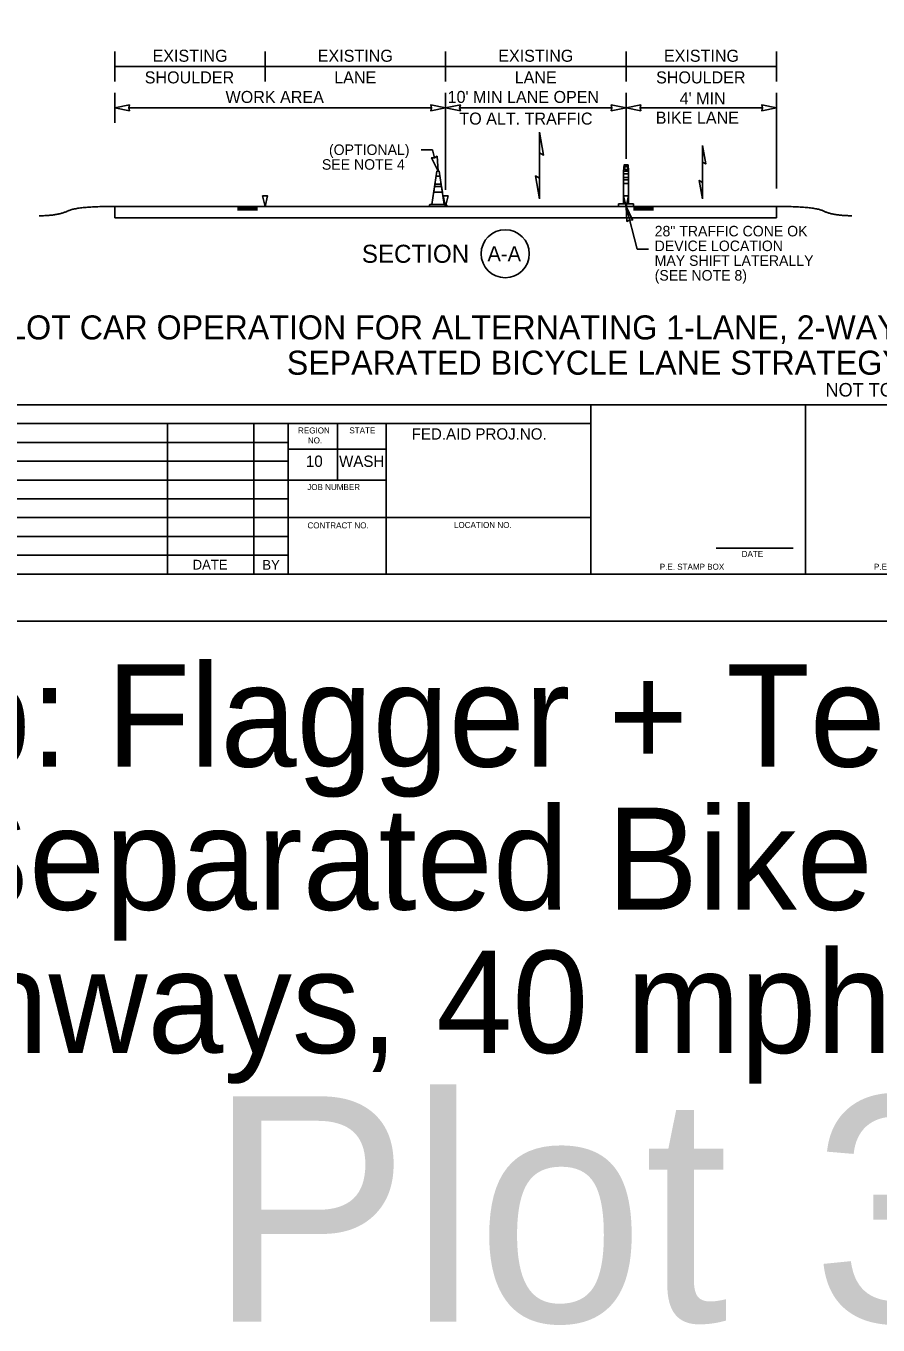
# Model space of a CAD drawing. Extents: x 99998.9 to 100095.7, y 99995 to 100010.7.
# Drawn here: x 100043.7 to 100049.37, y 99995.01 to 100003.65 of the extents above; entities that cross this region are included whole.
import ezdxf

# ---------------------------------------------------------------- set-up
doc = ezdxf.new("R2010")
doc.units = 0
for name, color, linetype in [('SH_DE_DetailHeading1Text', 7, 'Continuous'), ('SH_GI_PlotLimits', 7, 'Continuous'), ('SH_GI_SheetBorder', 7, 'Continuous'), ('SH_GI_SheetLocationText', 7, 'Continuous'), ('SH_GI_SheetTextInCells', 7, 'Continuous'), ('TR_WZ_TrafficConeElev', 7, 'Continuous'), ('TR_WZ_TubularMarkerElev', 7, 'Continuous'), ('TR_WZ_WorkZoneDetails', 7, 'Continuous'), ('TR_WZ_WorkZoneTextCurrent', 7, 'Continuous')]:
    doc.layers.add(name, color=color, linetype=linetype)

msp = doc.modelspace()

# ---------------------------------------------------------------- linework, layer by layer
at = {"layer": 'SH_GI_PlotLimits'}
msp.add_lwpolyline([(100039.0625, 99999.6875), (100056.0625, 99999.6875), (100056.0625, 100010.6875), (100039.0625, 100010.6875)], close=True, dxfattribs=at)
at = {"layer": 'SH_GI_SheetBorder'}
for p, q in [((100040, 100001.1259), (100055.75, 100001.1259)), ((100047.4566, 100000), (100047.4566, 100001.1259)), ((100048.8828, 100000), (100048.8828, 100001.1259)), ((100040, 100001.0008), (100047.4566, 100001.0008)), ((100044.641, 100001.0008), (100044.641, 100000)), ((100045.2164, 100001.0008), (100045.2164, 100000)), ((100045.4451, 100001.0008), (100045.4451, 100000)), ((100045.7719, 100000.6255), (100045.7719, 100001.0008)), ((100046.0956, 100000), (100046.0956, 100001.0008)), ((100042.1821, 100000.8757), (100045.4466, 100000.8757)), ((100042.1821, 100000.7506), (100045.4466, 100000.7506)), ((100046.0958, 100000.831), (100045.4466, 100000.831)), ((100040, 100000.6255), (100045.4466, 100000.6255)), ((100046.0958, 100000.6255), (100045.4466, 100000.6255)), ((100040, 100000.5004), (100045.4466, 100000.5004)), ((100040, 100000.3753), (100045.4466, 100000.3753)), ((100047.4566, 100000.3753), (100045.4466, 100000.3753)), ((100040, 100000.2502), (100045.4466, 100000.2502)), ((100048.2903, 100000.1733), (100048.802, 100000.1733)), ((100040, 100000.1251), (100045.4466, 100000.1251)), ((100040, 100000), (100055.75, 100000))]:
    msp.add_line(p, q, dxfattribs=at)
at = {"layer": 'TR_WZ_TrafficConeElev'}
for p, q in [((100046.4173, 100002.5768), (100046.4116, 100002.5393)), ((100046.4642, 100002.5768), (100046.4173, 100002.5768)), ((100046.4282, 100002.6476), (100046.4199, 100002.5934)), ((100046.4199, 100002.5934), (100046.4617, 100002.5934)), ((100046.4534, 100002.6476), (100046.4282, 100002.6476)), ((100046.4617, 100002.5934), (100046.4534, 100002.6476)), ((100046.47, 100002.5393), (100046.4642, 100002.5768)), ((100046.4116, 100002.5393), (100046.47, 100002.5393)), ((100046.3871, 100002.458), (100046.383, 100002.4538)), ((100046.383, 100002.4538), (100046.383, 100002.4455)), ((100046.383, 100002.4455), (100046.4986, 100002.4455)), ((100046.3991, 100002.458), (100046.3871, 100002.458)), ((100046.4986, 100002.4538), (100046.4944, 100002.458)), ((100046.4986, 100002.4455), (100046.4986, 100002.4538))]:
    msp.add_line(p, q, dxfattribs=at)
msp.add_lwpolyline([(100046.3991, 100002.458), (100046.4824, 100002.458), (100046.4486, 100002.6788), (100046.433, 100002.6788)], close=True, dxfattribs=at)
msp.add_lwpolyline([(100046.3991, 100002.458), (100046.4824, 100002.458), (100046.4486, 100002.6788), (100046.433, 100002.6788)], close=True, dxfattribs=at)
msp.add_lwpolyline([(100046.4944, 100002.458), (100046.4824, 100002.458), (100046.3991, 100002.458)], dxfattribs=at)
at = {"layer": 'TR_WZ_TubularMarkerElev'}
for p, q in [((100047.7074, 100002.6625), (100047.6741, 100002.6625)), ((100047.6741, 100002.6625), (100047.6741, 100002.6379)), ((100047.6743, 100002.6788), (100047.7072, 100002.6788)), ((100047.6824, 100002.7112), (100047.6998, 100002.7112)), ((100047.6998, 100002.689), (100047.6824, 100002.689)), ((100047.7074, 100002.6379), (100047.7074, 100002.6625)), ((100047.6741, 100002.6379), (100047.7074, 100002.6379)), ((100047.6741, 100002.6215), (100047.6741, 100002.597)), ((100047.7074, 100002.6215), (100047.6741, 100002.6215)), ((100047.6741, 100002.597), (100047.7074, 100002.597)), ((100047.7074, 100002.597), (100047.7074, 100002.6215)), ((100047.6408, 100002.4619), (100047.6408, 100002.4455)), ((100047.6408, 100002.4455), (100047.7408, 100002.4455)), ((100047.7408, 100002.4455), (100047.7408, 100002.4619))]:
    msp.add_line(p, q, dxfattribs=at)
for points in [[(100047.6741, 100002.4619), (100047.7074, 100002.4619), (100047.7074, 100002.6747)], [(100047.6741, 100002.6747), (100047.6741, 100002.4619)], [(100047.6741, 100002.4619), (100047.7074, 100002.4619), (100047.7074, 100002.6747)], [(100047.6741, 100002.6747), (100047.6741, 100002.4619)], [(100047.7072, 100002.6788), (100047.6743, 100002.6788), (100047.7072, 100002.6788), (100047.6743, 100002.6788)], [(100047.7072, 100002.6788), (100047.6743, 100002.6788), (100047.7072, 100002.6788), (100047.6743, 100002.6788)], [(100047.7408, 100002.4619), (100047.7074, 100002.4619), (100047.6741, 100002.4619), (100047.6408, 100002.4619)]]:
    msp.add_lwpolyline(points, dxfattribs=at)
msp.add_lwpolyline([(100047.6743, 100002.6788), (100047.6774, 100002.7213), (100047.7044, 100002.7213), (100047.7072, 100002.6788)], close=True, dxfattribs=at)
for centre, major_axis, ratio, start_param, end_param in [((100047.6744, 100002.6738), (0, 0.00512), 0.053405, 0.177149, 1.393647), ((100047.6744, 100002.6738), (0, 0.00512), 0.053405, 0.177149, 1.393647), ((100047.6824, 100002.7001), (0, 0.0111), 0.071484, 0, 3.141593), ((100047.6998, 100002.7001), (0, 0.0111), 0.071484, 3.141593, 6.283185), ((100047.7072, 100002.6738), (0, 0.00512), 0.053405, 4.889538, 6.106036), ((100047.7072, 100002.6738), (0, 0.00512), 0.053405, 4.889538, 6.106036)]:
    msp.add_ellipse(centre, major_axis=major_axis, ratio=ratio, start_param=start_param, end_param=end_param, dxfattribs=at)
at = {"layer": 'TR_WZ_WorkZoneDetails'}
for p, q in [((100044.2907, 100003.2755), (100044.2907, 100003.4755)), ((100045.2907, 100003.2755), (100045.2907, 100003.4755)), ((100046.4907, 100003.2755), (100046.4907, 100003.4755)), ((100047.6907, 100003.2755), (100047.6907, 100003.4755)), ((100048.6907, 100003.2755), (100048.6907, 100003.4755)), ((100044.2907, 100003.3755), (100045.2907, 100003.3755)), ((100045.2907, 100003.3755), (100046.4907, 100003.3755)), ((100046.4907, 100003.3755), (100047.6907, 100003.3755)), ((100047.6907, 100003.3755), (100048.6907, 100003.3755)), ((100044.2907, 100003.0015), (100044.2907, 100003.2015)), ((100046.4907, 100002.5552), (100046.4907, 100003.2015)), ((100047.6907, 100002.7613), (100047.6907, 100003.2015)), ((100048.6907, 100002.5652), (100048.6907, 100003.2015)), ((100046.397, 100003.1015), (100044.3844, 100003.1015)), ((100047.5969, 100003.1015), (100046.5844, 100003.1015)), ((100048.597, 100003.1015), (100047.7844, 100003.1015)), ((100046.3275, 100002.8215), (100046.4037, 100002.8215)), ((100046.4172, 100002.7696), (100046.4037, 100002.8215)), ((100047.1157, 100002.8019), (100047.1157, 100002.6331)), ((100047.1157, 100002.6331), (100047.1157, 100002.8019)), ((100048.199, 100002.7406), (100048.199, 100002.6055)), ((100048.199, 100002.6055), (100048.199, 100002.7406)), ((100044.2907, 100002.4454), (100044.2907, 100002.3704)), ((100048.6907, 100002.4454), (100044.2907, 100002.4454)), ((100045.1077, 100002.4402), (100045.2407, 100002.4402)), ((100045.1077, 100002.4346), (100045.2407, 100002.4346)), ((100045.1077, 100002.4289), (100045.2407, 100002.4289)), ((100045.1077, 100002.4237), (100045.2407, 100002.4237)), ((100047.6907, 100002.4454), (100047.7647, 100002.1601)), ((100047.8737, 100002.4398), (100047.7407, 100002.4398)), ((100047.8737, 100002.4342), (100047.7407, 100002.4342)), ((100047.8737, 100002.4285), (100047.7407, 100002.4285)), ((100047.8737, 100002.4233), (100047.7407, 100002.4233)), ((100048.6907, 100002.4454), (100048.6907, 100002.3704)), ((100048.6907, 100002.3704), (100044.2907, 100002.3704)), ((100047.841, 100002.1601), (100047.7647, 100002.1601))]:
    msp.add_line(p, q, dxfattribs=at)
for points in [[(100044.2907, 100003.1015), (100044.389, 100003.0822), (100044.3844, 100003.1015), (100044.389, 100003.1208)], [(100046.4907, 100003.1015), (100046.3924, 100003.0822), (100046.397, 100003.1015), (100046.3924, 100003.1208)], [(100046.4907, 100003.1015), (100046.589, 100003.0822), (100046.5844, 100003.1015), (100046.589, 100003.1208)], [(100047.6907, 100003.1015), (100047.5924, 100003.0822), (100047.5969, 100003.1015), (100047.5924, 100003.1208)], [(100047.6907, 100003.1015), (100047.7889, 100003.0822), (100047.7844, 100003.1015), (100047.7889, 100003.1208)], [(100048.6907, 100003.1015), (100048.5924, 100003.0822), (100048.597, 100003.1015), (100048.5924, 100003.1208)], [(100047.1157, 100002.9395), (100047.1427, 100002.7863), (100047.1157, 100002.8019)], [(100048.199, 100002.8507), (100048.2206, 100002.7281), (100048.199, 100002.7406)], [(100046.4408, 100002.6788), (100046.3975, 100002.7692), (100046.4173, 100002.7696), (100046.4348, 100002.7788)], [(100047.1157, 100002.4954), (100047.0887, 100002.6487), (100047.1157, 100002.6331)], [(100048.199, 100002.4954), (100048.1774, 100002.618), (100048.199, 100002.6055)], [(100045.2907, 100002.4454), (100045.274, 100002.5152), (100045.3073, 100002.5152)], [(100046.4907, 100002.4454), (100046.474, 100002.5152), (100046.5074, 100002.5152)], [(100047.6907, 100002.4454), (100047.674, 100002.5152), (100047.7073, 100002.5152)], [(100047.6907, 100002.4454), (100047.734, 100002.3551), (100047.7142, 100002.3547), (100047.6967, 100002.3455)]]:
    msp.add_lwpolyline(points, close=True, dxfattribs=at)
for points in [[(100045.3073, 100002.5152), (100045.274, 100002.5152), (100045.2907, 100002.4454), (100045.3073, 100002.5152)], [(100046.5074, 100002.5152), (100046.474, 100002.5152), (100046.4907, 100002.4454), (100046.5074, 100002.5152)], [(100047.7073, 100002.5152), (100047.674, 100002.5152), (100047.6907, 100002.4454), (100047.7073, 100002.5152)]]:
    msp.add_lwpolyline(points, dxfattribs=at)
msp.add_circle((100046.8872, 100002.1305), 0.16, dxfattribs=at)
for points in [[(100044.2907, 100002.4454), (100044.0395, 100002.4454), (100043.914, 100002.3833), (100043.7886, 100002.3833)], [(100048.6907, 100002.4454), (100048.9419, 100002.4456), (100049.0674, 100002.3835), (100049.1928, 100002.3836)]]:
    msp.add_open_spline(points, degree=2, dxfattribs=at)

# ---------------------------------------------------------------- texts
at = {"layer": 'SH_DE_DetailHeading1Text'}
for s, height, p in [('PILOT CAR OPERATION FOR ALTERNATING 1-LANE, 2-WAY TRAFFIC: FLAGGER-CONTROLLED + TEMP. RUMBLE STRIPS', 0.16, (100043.3806, 100001.5606)), ('SEPARATED BICYCLE LANE STRATEGY (HIGHWAYS, 40 MPH OR LESS)', 0.16, (100045.435, 100001.3259)), ('NOT TO SCALE', 0.09, (100049.0168, 100001.1809))]:
    msp.add_text(s, height=height, rotation=360, dxfattribs=at).set_placement(p)
at = {"layer": 'SH_GI_SheetLocationText'}
for s, height, p in [('Pilot Car Op: Flagger + Temp Rum. Strips', 0.68, (100038.7792, 99998.7191)), ('Separated Bike Lane', 0.68, (100043.1141, 99997.7671)), ('(Highways, 40 mph or Less)', 0.68, (100041.6785, 99996.8151)), ('Plot 3', 1.5, (100044.9133, 99995.0267))]:
    msp.add_text(s, height=height, dxfattribs=at).set_placement(p)
at = {"layer": 'SH_GI_SheetTextInCells'}
for s, height, p in [('REGION', 0.04003, (100045.5099, 100000.9352)), ('STATE', 0.04003, (100045.8511, 100000.9357)), ('FED.AID PROJ.NO.', 0.07506, (100046.2652, 100000.8945)), ('NO.', 0.04003, (100045.5752, 100000.869)), ('10', 0.07506, (100045.5621, 100000.7131)), ('WASH', 0.07506, (100045.7826, 100000.7131)), ('JOB NUMBER', 0.04003, (100045.5712, 100000.5587)), ('CONTRACT NO.', 0.040032, (100045.5725, 100000.3037)), ('LOCATION NO.', 0.040032, (100046.5465, 100000.3067)), ('DATE', 0.04003, (100048.4597, 100000.1141)), ('DATE', 0.06505, (100044.8091, 100000.03)), ('BY', 0.06505, (100045.2725, 100000.0285)), ('P.E. STAMP BOX', 0.040032, (100047.915, 100000.0286)), ('P.E. STAMP BOX', 0.040032, (100049.339, 100000.0286))]:
    msp.add_text(s, height=height, dxfattribs=at).set_placement(p)
at = {"layer": 'TR_WZ_WorkZoneDetails'}
for s, height, p in [('EXISTING', 0.08, (100044.5424, 100003.4075)), ('EXISTING', 0.08, (100045.6409, 100003.4075)), ('EXISTING', 0.08, (100046.8409, 100003.4075)), ('EXISTING', 0.08, (100047.9424, 100003.4075)), ('SHOULDER', 0.08, (100044.4905, 100003.2635)), ('LANE', 0.08, (100045.7503, 100003.2635)), ('LANE', 0.08, (100046.9503, 100003.2635)), ('SHOULDER', 0.08, (100047.8905, 100003.2635)), ('SECTION', 0.12, (100045.9342, 100002.0705)), ('A-A', 0.1, (100046.7694, 100002.0805))]:
    msp.add_text(s, height=height, rotation=360, dxfattribs=at).set_placement(p)
for s, p in [('WORK AREA', (100045.0278, 100003.1335)), ("10' MIN LANE OPEN", (100046.5043, 100003.1335)), ("4' MIN", (100048.0471, 100003.1235)), ('TO ALT. TRAFFIC', (100046.5824, 100002.9895)), ('BIKE LANE', (100047.8881, 100002.9955))]:
    msp.add_text(s, height=0.08, dxfattribs=at).set_placement(p)
at = {"layer": 'TR_WZ_WorkZoneTextCurrent'}
for s, p in [('(OPTIONAL)', (100045.7154, 100002.7875)), ('SEE NOTE 4', (100045.6685, 100002.6895)), ('28" TRAFFIC CONE OK', (100047.881, 100002.2461)), ('DEVICE LOCATION', (100047.881, 100002.1481)), ('MAY SHIFT LATERALLY ', (100047.881, 100002.0501)), ('(SEE NOTE 8)', (100047.881, 100001.9521))]:
    msp.add_text(s, height=0.07, dxfattribs=at).set_placement(p)

doc.saveas('drawing.dxf')
